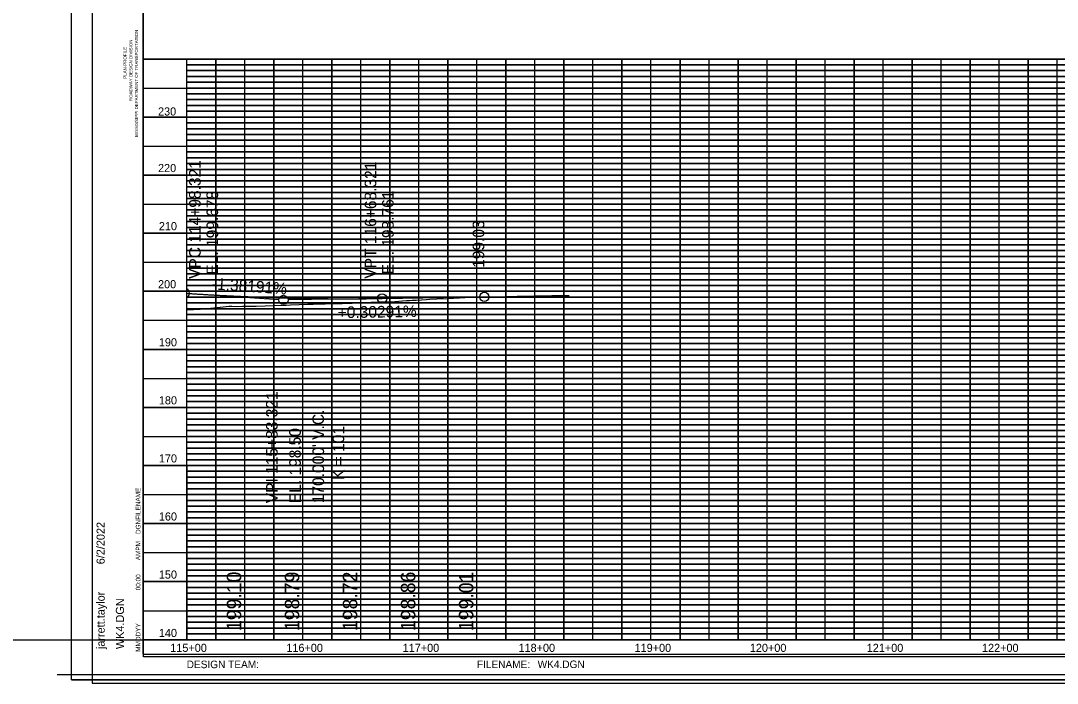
# Model space of a CAD drawing. Extents: x 1383694 to 1386843, y 1973227 to 1975727.
# Drawn here: x 1385051 to 1385944, y 1974440 to 1975010 of the extents above; entities that cross this region are included whole.
import ezdxf

# ---------------------------------------------------------------- set-up
doc = ezdxf.new("R2010")
doc.units = 0
for name, color, linetype in [('Default', 7, 'Continuous'), ('PROFILE_CELL', 7, 'Continuous'), ('PROFILES_1', 7, 'Continuous'), ('PROFILES_TX_GRADES', 7, 'Continuous'), ('PROFILES_TX_VPI', 7, 'Continuous'), ('R_Border', 7, 'Continuous'), ('R_Grid', 7, 'Continuous'), ('R_No Plot', 7, 'Continuous'), ('SHEET_BORDER', 7, 'Continuous'), ('SHEET_BORDER_GRIDS', 7, 'Continuous'), ('SHEET_BORDER_TX', 7, 'Continuous'), ('SHEET_DATE_DGN_TX', 7, 'Continuous'), ('SHEET_PLOTTING_SHAPE', 7, 'Continuous'), ('X_PROFILES_1', 7, 'Continuous')]:
    doc.layers.add(name, color=color, linetype=linetype)

msp = doc.modelspace()

# ---------------------------------------------------------------- linework, layer by layer
at = {"layer": 'PROFILE_CELL'}
msp.add_line((1383694.23, 1974477.44), (1385594.23, 1974477.44), dxfattribs=at)
at = {"layer": 'PROFILES_1'}
msp.add_line((1385362.56, 1974771.25), (1385450.61, 1974772.58), dxfattribs=at)
msp.add_spline([(1385194.23, 1974775.72), (1385195.96, 1974775.6), (1385199.36, 1974775.37), (1385202.76, 1974775.15), (1385206.16, 1974774.94), (1385209.56, 1974774.73), (1385212.96, 1974774.52), (1385216.36, 1974774.33), (1385219.76, 1974774.13), (1385223.16, 1974773.95), (1385226.56, 1974773.77), (1385229.96, 1974773.59), (1385233.36, 1974773.42), (1385236.76, 1974773.26), (1385240.16, 1974773.1), (1385243.56, 1974772.95), (1385246.96, 1974772.81), (1385250.36, 1974772.66), (1385253.76, 1974772.53), (1385257.16, 1974772.4), (1385260.56, 1974772.28), (1385263.96, 1974772.16), (1385267.36, 1974772.05), (1385270.76, 1974771.94), (1385274.16, 1974771.84), (1385277.56, 1974771.75), (1385280.96, 1974771.66), (1385284.36, 1974771.58), (1385287.76, 1974771.5), (1385291.16, 1974771.43), (1385294.56, 1974771.36), (1385297.96, 1974771.3), (1385301.36, 1974771.25), (1385304.76, 1974771.2), (1385308.16, 1974771.15), (1385311.56, 1974771.12), (1385314.96, 1974771.09), (1385318.36, 1974771.06), (1385321.76, 1974771.04), (1385325.16, 1974771.03), (1385328.56, 1974771.02), (1385331.96, 1974771.01), (1385335.36, 1974771.02), (1385338.76, 1974771.02), (1385342.16, 1974771.04), (1385345.56, 1974771.06), (1385348.96, 1974771.08), (1385352.36, 1974771.12), (1385355.76, 1974771.15), (1385359.16, 1974771.2), (1385362.56, 1974771.25)], degree=3, dxfattribs=at)
at = {"layer": 'PROFILES_TX_GRADES'}
for p, q in [((1385194.23, 1974775.71), (1385273.57, 1974770.23)), ((1385362.56, 1974771.25), (1385281.56, 1974770.02))]:
    msp.add_line(p, q, dxfattribs=at)
for centre in [(1385277.56, 1974769.96), (1385362.56, 1974771.25), (1385450.61, 1974772.58)]:
    msp.add_circle(centre, 4, dxfattribs=at)
msp.add_arc((1385192.56, 1974775.83), 4, 294.81571, 65.18429, dxfattribs=at)
at = {"layer": 'R_Border'}
for p, q in [((1385156.93, 1974462.74), (1385156.93, 1975490.04)), ((1386737.83, 1974977.44), (1385156.93, 1974977.44)), ((1385194.23, 1974477.44), (1385194.23, 1974977.44)), ((1385244.23, 1974477.44), (1385244.23, 1974977.44)), ((1385294.23, 1974477.44), (1385294.23, 1974977.44)), ((1385344.23, 1974477.44), (1385344.23, 1974977.44)), ((1385394.23, 1974477.44), (1385394.23, 1974977.44)), ((1385444.23, 1974477.44), (1385444.23, 1974977.44)), ((1385494.23, 1974477.44), (1385494.23, 1974977.44)), ((1385544.23, 1974477.44), (1385544.23, 1974977.44)), ((1385594.23, 1974477.44), (1385594.23, 1974977.44)), ((1385644.23, 1974477.44), (1385644.23, 1974977.44)), ((1385694.23, 1974477.44), (1385694.23, 1974977.44)), ((1385744.23, 1974477.44), (1385744.23, 1974977.44)), ((1385794.23, 1974477.44), (1385794.23, 1974977.44)), ((1385844.23, 1974477.44), (1385844.23, 1974977.44)), ((1385894.23, 1974477.44), (1385894.23, 1974977.44)), ((1386737.83, 1974927.44), (1385156.93, 1974927.44)), ((1386737.83, 1974877.44), (1385156.93, 1974877.44)), ((1386737.83, 1974827.44), (1385156.93, 1974827.44)), ((1386737.83, 1974777.44), (1385156.93, 1974777.44)), ((1386737.83, 1974727.44), (1385156.93, 1974727.44)), ((1386737.83, 1974677.44), (1385156.93, 1974677.44)), ((1386737.83, 1974627.44), (1385156.93, 1974627.44)), ((1386737.83, 1974577.44), (1385156.93, 1974577.44)), ((1386737.83, 1974527.44), (1385156.93, 1974527.44)), ((1386737.83, 1974477.44), (1385156.93, 1974477.44)), ((1385156.93, 1974462.74), (1385156.93, 1974462.74)), ((1386737.83, 1974462.74), (1385156.93, 1974462.74))]:
    msp.add_line(p, q, dxfattribs=at)
at = {"layer": 'R_Grid'}
for p, q in [((1385219.23, 1974477.44), (1385219.23, 1974977.44)), ((1385269.23, 1974477.44), (1385269.23, 1974977.44)), ((1385319.23, 1974477.44), (1385319.23, 1974977.44)), ((1385369.23, 1974477.44), (1385369.23, 1974977.44)), ((1385419.23, 1974477.44), (1385419.23, 1974977.44)), ((1385469.23, 1974477.44), (1385469.23, 1974977.44)), ((1385519.23, 1974477.44), (1385519.23, 1974977.44)), ((1385569.23, 1974477.44), (1385569.23, 1974977.44)), ((1385619.23, 1974477.44), (1385619.23, 1974977.44)), ((1385669.23, 1974477.44), (1385669.23, 1974977.44)), ((1385719.23, 1974477.44), (1385719.23, 1974977.44)), ((1385769.23, 1974477.44), (1385769.23, 1974977.44)), ((1385819.23, 1974477.44), (1385819.23, 1974977.44)), ((1385869.23, 1974477.44), (1385869.23, 1974977.44)), ((1385919.23, 1974477.44), (1385919.23, 1974977.44)), ((1386694.23, 1974972.44), (1385194.23, 1974972.44)), ((1386694.23, 1974967.44), (1385194.23, 1974967.44)), ((1386694.23, 1974962.44), (1385194.23, 1974962.44)), ((1386694.23, 1974957.44), (1385194.23, 1974957.44)), ((1386694.23, 1974952.44), (1385194.23, 1974952.44)), ((1386694.23, 1974947.44), (1385194.23, 1974947.44)), ((1386694.23, 1974942.44), (1385194.23, 1974942.44)), ((1386694.23, 1974937.44), (1385194.23, 1974937.44)), ((1386694.23, 1974932.44), (1385194.23, 1974932.44)), ((1386694.23, 1974922.44), (1385194.23, 1974922.44)), ((1386694.23, 1974917.44), (1385194.23, 1974917.44)), ((1386694.23, 1974912.44), (1385194.23, 1974912.44)), ((1386694.23, 1974907.44), (1385194.23, 1974907.44)), ((1386694.23, 1974902.44), (1385194.23, 1974902.44)), ((1386694.23, 1974897.44), (1385194.23, 1974897.44)), ((1386694.23, 1974892.44), (1385194.23, 1974892.44)), ((1386694.23, 1974887.44), (1385194.23, 1974887.44)), ((1386694.23, 1974882.44), (1385194.23, 1974882.44)), ((1386694.23, 1974872.44), (1385194.23, 1974872.44)), ((1386694.23, 1974867.44), (1385194.23, 1974867.44)), ((1386694.23, 1974862.44), (1385194.23, 1974862.44)), ((1386694.23, 1974857.44), (1385194.23, 1974857.44)), ((1386694.23, 1974852.44), (1385194.23, 1974852.44)), ((1386694.23, 1974847.44), (1385194.23, 1974847.44)), ((1386694.23, 1974842.44), (1385194.23, 1974842.44)), ((1386694.23, 1974837.44), (1385194.23, 1974837.44)), ((1386694.23, 1974832.44), (1385194.23, 1974832.44)), ((1386694.23, 1974822.44), (1385194.23, 1974822.44)), ((1386694.23, 1974817.44), (1385194.23, 1974817.44)), ((1386694.23, 1974812.44), (1385194.23, 1974812.44)), ((1386694.23, 1974807.44), (1385194.23, 1974807.44)), ((1386694.23, 1974802.44), (1385194.23, 1974802.44)), ((1386694.23, 1974797.44), (1385194.23, 1974797.44)), ((1386694.23, 1974792.44), (1385194.23, 1974792.44)), ((1386694.23, 1974787.44), (1385194.23, 1974787.44)), ((1386694.23, 1974782.44), (1385194.23, 1974782.44)), ((1386694.23, 1974772.44), (1385194.23, 1974772.44)), ((1386694.23, 1974767.44), (1385194.23, 1974767.44)), ((1386694.23, 1974762.44), (1385194.23, 1974762.44)), ((1386694.23, 1974757.44), (1385194.23, 1974757.44)), ((1386694.23, 1974752.44), (1385194.23, 1974752.44)), ((1386694.23, 1974747.44), (1385194.23, 1974747.44)), ((1386694.23, 1974742.44), (1385194.23, 1974742.44)), ((1386694.23, 1974737.44), (1385194.23, 1974737.44)), ((1386694.23, 1974732.44), (1385194.23, 1974732.44)), ((1386694.23, 1974722.44), (1385194.23, 1974722.44)), ((1386694.23, 1974717.44), (1385194.23, 1974717.44)), ((1386694.23, 1974712.44), (1385194.23, 1974712.44)), ((1386694.23, 1974707.44), (1385194.23, 1974707.44)), ((1386694.23, 1974702.44), (1385194.23, 1974702.44)), ((1386694.23, 1974697.44), (1385194.23, 1974697.44)), ((1386694.23, 1974692.44), (1385194.23, 1974692.44)), ((1386694.23, 1974687.44), (1385194.23, 1974687.44)), ((1386694.23, 1974682.44), (1385194.23, 1974682.44)), ((1386694.23, 1974672.44), (1385194.23, 1974672.44)), ((1386694.23, 1974667.44), (1385194.23, 1974667.44)), ((1386694.23, 1974662.44), (1385194.23, 1974662.44)), ((1386694.23, 1974657.44), (1385194.23, 1974657.44)), ((1386694.23, 1974652.44), (1385194.23, 1974652.44)), ((1386694.23, 1974647.44), (1385194.23, 1974647.44)), ((1386694.23, 1974642.44), (1385194.23, 1974642.44)), ((1386694.23, 1974637.44), (1385194.23, 1974637.44)), ((1386694.23, 1974632.44), (1385194.23, 1974632.44)), ((1386694.23, 1974622.44), (1385194.23, 1974622.44)), ((1386694.23, 1974617.44), (1385194.23, 1974617.44)), ((1386694.23, 1974612.44), (1385194.23, 1974612.44)), ((1386694.23, 1974607.44), (1385194.23, 1974607.44)), ((1386694.23, 1974602.44), (1385194.23, 1974602.44)), ((1386694.23, 1974597.44), (1385194.23, 1974597.44)), ((1386694.23, 1974592.44), (1385194.23, 1974592.44)), ((1386694.23, 1974587.44), (1385194.23, 1974587.44)), ((1386694.23, 1974582.44), (1385194.23, 1974582.44)), ((1386694.23, 1974572.44), (1385194.23, 1974572.44)), ((1386694.23, 1974567.44), (1385194.23, 1974567.44)), ((1386694.23, 1974562.44), (1385194.23, 1974562.44)), ((1386694.23, 1974557.44), (1385194.23, 1974557.44)), ((1386694.23, 1974552.44), (1385194.23, 1974552.44)), ((1386694.23, 1974547.44), (1385194.23, 1974547.44)), ((1386694.23, 1974542.44), (1385194.23, 1974542.44)), ((1386694.23, 1974537.44), (1385194.23, 1974537.44)), ((1386694.23, 1974532.44), (1385194.23, 1974532.44)), ((1386694.23, 1974522.44), (1385194.23, 1974522.44)), ((1386694.23, 1974517.44), (1385194.23, 1974517.44)), ((1386694.23, 1974512.44), (1385194.23, 1974512.44)), ((1386694.23, 1974507.44), (1385194.23, 1974507.44)), ((1386694.23, 1974502.44), (1385194.23, 1974502.44)), ((1386694.23, 1974497.44), (1385194.23, 1974497.44)), ((1386694.23, 1974492.44), (1385194.23, 1974492.44)), ((1386694.23, 1974487.44), (1385194.23, 1974487.44)), ((1386694.23, 1974482.44), (1385194.23, 1974482.44))]:
    msp.add_line(p, q, dxfattribs=at)
at = {"layer": 'R_No Plot'}
msp.add_line((1385094.93, 1974442.85), (1386761.6, 1974442.85), dxfattribs=at)
msp.add_lwpolyline([(1385094.93, 1975509.53), (1386761.63, 1975509.53), (1386761.63, 1974442.85), (1385094.93, 1974442.85)], close=True, dxfattribs=at)
at = {"layer": 'SHEET_BORDER'}
for p, q in [((1385156.73, 1974527.44), (1385156.73, 1975514.94)), ((1385156.73, 1974977.44), (1386831.73, 1974977.44)), ((1385194.23, 1974477.44), (1385194.23, 1974977.44)), ((1385156.73, 1974464.94), (1385156.73, 1974527.44)), ((1385194.23, 1974477.44), (1385156.73, 1974477.44)), ((1385194.23, 1974477.44), (1386831.73, 1974477.44)), ((1385244.23, 1974477.44), (1385244.23, 1974477.44)), ((1385156.73, 1974464.94), (1385245.13, 1974464.94)), ((1385244.23, 1974464.94), (1386831.73, 1974464.94)), ((1385082.73, 1974447.44), (1386842.73, 1974447.44)), ((1385112.73, 1974439.94), (1385112.73, 1974439.94))]:
    msp.add_line(p, q, dxfattribs=at)
for points in [[(1385156.73, 1975514.94), (1385156.73, 1974977.44), (1386831.73, 1974977.44), (1386831.73, 1975473.74), (1386695.93, 1975473.74), (1386695.93, 1975514.94)], [(1385194.23, 1974477.44), (1385194.23, 1974977.44), (1386794.23, 1974977.44), (1386794.23, 1974477.44)]]:
    msp.add_lwpolyline(points, close=True, dxfattribs=at)
at = {"layer": 'SHEET_BORDER_GRIDS'}
for p, q in [((1385219.23, 1974977.44), (1385219.23, 1974477.44)), ((1385244.23, 1974477.44), (1385244.23, 1974977.44)), ((1385269.23, 1974977.44), (1385269.23, 1974477.44)), ((1385294.23, 1974477.44), (1385294.23, 1974977.44)), ((1385319.23, 1974977.44), (1385319.23, 1974477.44)), ((1385344.23, 1974477.44), (1385344.23, 1974977.44)), ((1385369.23, 1974977.44), (1385369.23, 1974477.44)), ((1385394.23, 1974477.44), (1385394.23, 1974977.44)), ((1385419.23, 1974977.44), (1385419.23, 1974477.44)), ((1385444.23, 1974477.44), (1385444.23, 1974977.44)), ((1385469.23, 1974977.44), (1385469.23, 1974477.44)), ((1385494.23, 1974477.44), (1385494.23, 1974977.44)), ((1385519.23, 1974977.44), (1385519.23, 1974477.44)), ((1385544.23, 1974477.44), (1385544.23, 1974977.44)), ((1385569.23, 1974977.44), (1385569.23, 1974477.44)), ((1385594.23, 1974477.44), (1385594.23, 1974977.44)), ((1385619.23, 1974977.44), (1385619.23, 1974477.44)), ((1385644.23, 1974477.44), (1385644.23, 1974977.44)), ((1385669.23, 1974977.44), (1385669.23, 1974477.44)), ((1385694.23, 1974477.44), (1385694.23, 1974977.44)), ((1385719.23, 1974977.44), (1385719.23, 1974477.44)), ((1385744.23, 1974477.44), (1385744.23, 1974977.44)), ((1385769.23, 1974977.44), (1385769.23, 1974477.44)), ((1385794.23, 1974477.44), (1385794.23, 1974977.44)), ((1385819.23, 1974977.44), (1385819.23, 1974477.44)), ((1385844.23, 1974477.44), (1385844.23, 1974977.44)), ((1385869.23, 1974977.44), (1385869.23, 1974477.44)), ((1385894.23, 1974477.44), (1385894.23, 1974977.44)), ((1385919.23, 1974977.44), (1385919.23, 1974477.44)), ((1385944.23, 1974477.44), (1385944.23, 1974977.44)), ((1385194.23, 1974972.44), (1386794.23, 1974972.44)), ((1385194.23, 1974967.44), (1386794.23, 1974967.44)), ((1385194.23, 1974962.44), (1386794.23, 1974962.44)), ((1385156.73, 1974952.44), (1386831.73, 1974952.44)), ((1385194.23, 1974957.44), (1386794.23, 1974957.44)), ((1385194.23, 1974947.44), (1386794.23, 1974947.44)), ((1385194.23, 1974942.44), (1386794.23, 1974942.44)), ((1385194.23, 1974937.44), (1386794.23, 1974937.44)), ((1385194.23, 1974932.44), (1386794.23, 1974932.44)), ((1385156.73, 1974927.44), (1386831.73, 1974927.44)), ((1385194.23, 1974922.44), (1386794.23, 1974922.44)), ((1385194.23, 1974917.44), (1386794.23, 1974917.44)), ((1385194.23, 1974912.44), (1386794.23, 1974912.44)), ((1385194.23, 1974907.44), (1386794.23, 1974907.44)), ((1385156.73, 1974902.44), (1386831.73, 1974902.44)), ((1385194.23, 1974897.44), (1386794.23, 1974897.44)), ((1385194.23, 1974892.44), (1386794.23, 1974892.44)), ((1385194.23, 1974887.44), (1386794.23, 1974887.44)), ((1385194.23, 1974882.44), (1386794.23, 1974882.44)), ((1385156.73, 1974877.44), (1386831.73, 1974877.44)), ((1385194.23, 1974872.44), (1386794.23, 1974872.44)), ((1385194.23, 1974867.44), (1386794.23, 1974867.44)), ((1385194.23, 1974862.44), (1386794.23, 1974862.44)), ((1385156.73, 1974852.44), (1386831.73, 1974852.44)), ((1385194.23, 1974857.44), (1386794.23, 1974857.44)), ((1385194.23, 1974847.44), (1386794.23, 1974847.44)), ((1385194.23, 1974842.44), (1386794.23, 1974842.44)), ((1385194.23, 1974837.44), (1386794.23, 1974837.44)), ((1385156.73, 1974827.44), (1386831.73, 1974827.44)), ((1385194.23, 1974832.44), (1386794.23, 1974832.44)), ((1385194.23, 1974822.44), (1386794.23, 1974822.44)), ((1385194.23, 1974817.44), (1386794.23, 1974817.44)), ((1385194.23, 1974812.44), (1386794.23, 1974812.44)), ((1385194.23, 1974807.44), (1386794.23, 1974807.44)), ((1385156.73, 1974802.44), (1386831.73, 1974802.44)), ((1385194.23, 1974797.44), (1386794.23, 1974797.44)), ((1385194.23, 1974792.44), (1386794.23, 1974792.44)), ((1385194.23, 1974787.44), (1386794.23, 1974787.44)), ((1385194.23, 1974782.44), (1386794.23, 1974782.44)), ((1385156.73, 1974777.44), (1386831.73, 1974777.44)), ((1385194.23, 1974772.44), (1386794.23, 1974772.44)), ((1385194.23, 1974767.44), (1386794.23, 1974767.44)), ((1385194.23, 1974762.44), (1386794.23, 1974762.44)), ((1385194.23, 1974757.44), (1386794.23, 1974757.44)), ((1385156.73, 1974752.44), (1386831.73, 1974752.44)), ((1385194.23, 1974747.44), (1386794.23, 1974747.44)), ((1385194.23, 1974742.44), (1386794.23, 1974742.44)), ((1385194.23, 1974737.44), (1386794.23, 1974737.44)), ((1385156.73, 1974727.44), (1386831.73, 1974727.44)), ((1385194.23, 1974732.44), (1386794.23, 1974732.44)), ((1385194.23, 1974722.44), (1386794.23, 1974722.44)), ((1385194.23, 1974717.44), (1386794.23, 1974717.44)), ((1385194.23, 1974712.44), (1386794.23, 1974712.44)), ((1385156.73, 1974702.44), (1386831.73, 1974702.44)), ((1385194.23, 1974707.44), (1386794.23, 1974707.44)), ((1385194.23, 1974697.44), (1386794.23, 1974697.44)), ((1385194.23, 1974692.44), (1386794.23, 1974692.44)), ((1385194.23, 1974687.44), (1386794.23, 1974687.44)), ((1385194.23, 1974682.44), (1386794.23, 1974682.44)), ((1385156.73, 1974677.44), (1386831.73, 1974677.44)), ((1385194.23, 1974672.44), (1386794.23, 1974672.44)), ((1385194.23, 1974667.44), (1386794.23, 1974667.44)), ((1385194.23, 1974662.44), (1386794.23, 1974662.44)), ((1385194.23, 1974657.44), (1386794.23, 1974657.44)), ((1385156.73, 1974652.44), (1386831.73, 1974652.44)), ((1385194.23, 1974647.44), (1386794.23, 1974647.44)), ((1385194.23, 1974642.44), (1386794.23, 1974642.44)), ((1385194.23, 1974637.44), (1386794.23, 1974637.44)), ((1385194.23, 1974632.44), (1386794.23, 1974632.44)), ((1385156.73, 1974627.44), (1386831.73, 1974627.44)), ((1385194.23, 1974622.44), (1386794.23, 1974622.44)), ((1385194.23, 1974617.44), (1386794.23, 1974617.44)), ((1385194.23, 1974612.44), (1386794.23, 1974612.44)), ((1385156.73, 1974602.44), (1386831.73, 1974602.44)), ((1385194.23, 1974607.44), (1386794.23, 1974607.44)), ((1385194.23, 1974597.44), (1386794.23, 1974597.44)), ((1385194.23, 1974592.44), (1386794.23, 1974592.44)), ((1385194.23, 1974587.44), (1386794.23, 1974587.44)), ((1385156.73, 1974577.44), (1386831.73, 1974577.44)), ((1385194.23, 1974582.44), (1386794.23, 1974582.44)), ((1385194.23, 1974572.44), (1386794.23, 1974572.44)), ((1385194.23, 1974567.44), (1386794.23, 1974567.44)), ((1385194.23, 1974562.44), (1386794.23, 1974562.44)), ((1385194.23, 1974557.44), (1386794.23, 1974557.44)), ((1385156.73, 1974552.44), (1386831.73, 1974552.44)), ((1385194.23, 1974547.44), (1386794.23, 1974547.44)), ((1385194.23, 1974542.44), (1386794.23, 1974542.44)), ((1385194.23, 1974537.44), (1386794.23, 1974537.44)), ((1385194.23, 1974532.44), (1386794.23, 1974532.44)), ((1385156.73, 1974527.44), (1386794.23, 1974527.44)), ((1385194.23, 1974522.44), (1386794.23, 1974522.44)), ((1385194.23, 1974517.44), (1386794.23, 1974517.44)), ((1385194.23, 1974512.44), (1386794.23, 1974512.44)), ((1385194.23, 1974507.44), (1386794.23, 1974507.44)), ((1385156.73, 1974502.44), (1386794.23, 1974502.44)), ((1385194.23, 1974497.44), (1386794.23, 1974497.44)), ((1385194.23, 1974492.44), (1386794.23, 1974492.44)), ((1385194.23, 1974487.44), (1386794.23, 1974487.44)), ((1385194.23, 1974482.44), (1386794.23, 1974482.44))]:
    msp.add_line(p, q, dxfattribs=at)
msp.add_lwpolyline([(1385194.23, 1974627.44), (1385194.23, 1974477.44), (1386794.23, 1974477.44), (1386794.23, 1974627.44)], close=True, dxfattribs=at)
at = {"layer": 'SHEET_PLOTTING_SHAPE'}
msp.add_lwpolyline([(1385112.73, 1974439.94), (1386842.73, 1974439.94), (1386842.73, 1975539.94), (1385112.73, 1975539.94)], close=True, dxfattribs=at)
at = {"layer": 'X_PROFILES_1'}
for points in [[(1385194.23, 1974761.42), (1385205.91, 1974762.09), (1385208.1, 1974762.19), (1385211.77, 1974762.48), (1385220.55, 1974763.6), (1385230.81, 1974764.56), (1385233.17, 1974764.7), (1385237.19, 1974764.2), (1385242.21, 1974764.49), (1385253.94, 1974764.59), (1385261.75, 1974764.99), (1385269.71, 1974765.12), (1385280, 1974765.51), (1385283.68, 1974765.67), (1385298.47, 1974766.27), (1385298.55, 1974766.28), (1385303.17, 1974766.39), (1385313.22, 1974766.65), (1385313.6, 1974766.66), (1385328.27, 1974766.84), (1385336.82, 1974767.14), (1385343.54, 1974767.38), (1385353.14, 1974767.94), (1385356.31, 1974768.1), (1385358.56, 1974768.18), (1385359.92, 1974768.28), (1385373.53, 1974768.76), (1385383.69, 1974769.4), (1385386.2, 1974769.54), (1385388.57, 1974769.68), (1385391.84, 1974769.9), (1385396.61, 1974770.19), (1385400.82, 1974770.45), (1385403.69, 1974770.62), (1385409.8, 1974770.82), (1385418.71, 1974771.17), (1385418.8, 1974771.18), (1385419.02, 1974771.19), (1385429.38, 1974771.72), (1385433.76, 1974771.95), (1385444.45, 1974772.38), (1385447.18, 1974772.5), (1385447.79, 1974772.52), (1385448.07, 1974772.53), (1385448.77, 1974772.55), (1385449.35, 1974772.56), (1385449.52, 1974772.56), (1385449.83, 1974772.57), (1385450.61, 1974772.58), (1385455.6, 1974772.66), (1385461.58, 1974772.74), (1385463.78, 1974772.79), (1385468.55, 1974772.89), (1385478.79, 1974773.12), (1385483.5, 1974773.29), (1385493.79, 1974773.63), (1385494.39, 1974773.63), (1385495.99, 1974773.66), (1385508.8, 1974773.83), (1385516.28, 1974773.78)], [(1385516.28, 1974773.78), (1385520.77, 1974773.73), (1385523.62, 1974773.75), (1385523.85, 1974773.75)]]:
    msp.add_lwpolyline(points, dxfattribs=at)

# ---------------------------------------------------------------- texts
at = {"layer": 'Default'}
for s, p in [('230', (1385169.54, 1974928.78)), ('220', (1385169.54, 1974880.04)), ('210', (1385170.24, 1974830.04)), ('200', (1385169.54, 1974780.04)), ('190', (1385170.24, 1974730.04)), ('180', (1385170.24, 1974680.04)), ('170', (1385170.24, 1974630.04)), ('160', (1385170.24, 1974580.04)), ('150', (1385170.24, 1974530.04)), ('140', (1385170.24, 1974479.75)), ('115+00', (1385180.08, 1974466.92)), ('116+00', (1385280.08, 1974466.92)), ('117+00', (1385380.28, 1974466.92)), ('118+00', (1385480.08, 1974466.92)), ('119+00', (1385580.08, 1974466.92)), ('120+00', (1385679.38, 1974466.92)), ('121+00', (1385780.08, 1974466.92)), ('122+00', (1385879.38, 1974466.92))]:
    msp.add_text(s, height=7, dxfattribs=at).set_placement(p)
for s, p in [('199.10', (1385241.23, 1974484.94)), ('198.79', (1385291.23, 1974484.94)), ('198.72', (1385341.23, 1974484.94)), ('198.86', (1385391.23, 1974484.94)), ('199.01', (1385441.23, 1974484.94))]:
    msp.add_text(s, height=12.5, rotation=90, dxfattribs=at).set_placement(p)
at = {"layer": 'PROFILES_TX_GRADES'}
for s, rotation, p in [('-1.38191%', 356.04741, (1385215.71, 1974779.13)), ('+0.30291%', 0.86772, (1385324.41, 1974754.28))]:
    msp.add_text(s, height=10, rotation=rotation, dxfattribs=at).set_placement(p)
at = {"layer": 'PROFILES_TX_VPI'}
for s, p in [('VPC 114+98.321', (1385206.3, 1974788.1)), ('VPT 116+68.321', (1385357.56, 1974788.33)), (' EL. 199.678', (1385221.3, 1974788.1)), (' EL. 198.761', (1385372.56, 1974788.33)), ('199.03', (1385450.61, 1974797.58)), ('VPI 115+83.321', (1385272.56, 1974594.96)), ("170.000' V.C.", (1385312.56, 1974594.96)), ('EL. 198.50', (1385292.56, 1974594.96)), ('K = 101', (1385329.91, 1974614.96))]:
    msp.add_text(s, height=10, rotation=90, dxfattribs=at).set_placement(p)
at = {"layer": 'R_Border'}
for s, p in [('6/2/2022', (1385123.59, 1974542.38)), ('jarrett.taylor', (1385123.59, 1974469.36)), ('WK4.DGN', (1385140.22, 1974469.36))]:
    msp.add_text(s, height=7, rotation=90, dxfattribs=at).set_placement(p)
at = {"layer": 'SHEET_BORDER_TX'}
for s, height, p in [('MISSISSIPPI DEPARTMENT OF TRANSPORTATION', 2.7501, (1385152.33, 1974910.39)), ('PLAN-PROFILE', 2.7498, (1385142.48, 1974960.44)), ('ROADWAY DESIGN DIVISION', 2.7498, (1385147.48, 1974941.19))]:
    msp.add_text(s, height=height, rotation=90, dxfattribs=at).set_placement(p)
for s, height, p in [('DESIGN TEAM:', 6.5001, (1385194.23, 1974452.94)), ('FILENAME:', 6.5, (1385444.23, 1974452.94)), ('WK4.DGN', 6.5, (1385496.56, 1974453.02))]:
    msp.add_text(s, height=height, dxfattribs=at).set_placement(p)
at = {"layer": 'SHEET_DATE_DGN_TX'}
for s, height, p in [('DGNFILENAME', 3.9999, (1385154.38, 1974568.44)), ('AMPM', 4, (1385154.38, 1974545.84)), ('00:00', 4, (1385154.38, 1974519.94)), ('MMDDYY', 4, (1385154.38, 1974467.04))]:
    msp.add_text(s, height=height, rotation=90, dxfattribs=at).set_placement(p)

doc.saveas('drawing.dxf')
